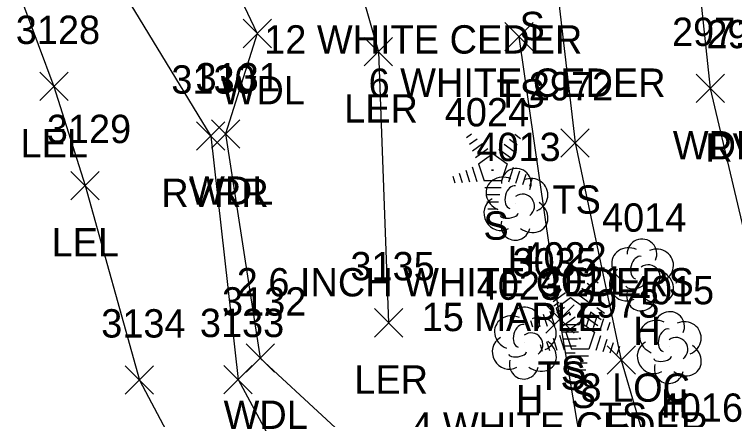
# Model space of a CAD drawing. Extents: x 1461855 to 1464118, y 556196 to 557441.
# Drawn here: x 1462111.2 to 1462162, y 556638.7 to 556667.3 of the extents above; entities that cross this region are included whole.
import ezdxf

# ---------------------------------------------------------------- set-up
doc = ezdxf.new("R2010")
doc.units = 0
for name, color, linetype in [('L_A', 7, 'Continuous'), ('L_C', 7, 'Continuous'), ('L_I', 7, 'Continuous'), ('L_TIC', 7, 'Continuous'), ('LARO', 7, 'Continuous'), ('LAWA', 7, 'Continuous'), ('LAWE', 7, 'Continuous'), ('LELB', 7, 'Continuous'), ('LTC', 7, 'Continuous'), ('LTD', 7, 'Continuous')]:
    doc.layers.add(name, color=color, linetype=linetype)

msp = doc.modelspace()

# ---------------------------------------------------------------- linework, layer by layer
at = {"layer": 'L_TIC'}
for points in [[(1462127.342, 556664.944), (1462129.342, 556666.944)], [(1462129.342, 556664.944), (1462127.342, 556666.944)], [(1462145.813, 556664.717), (1462147.813, 556666.717)], [(1462147.813, 556664.717), (1462145.813, 556666.717)], [(1462135.891, 556663.654), (1462137.891, 556665.654)], [(1462137.891, 556663.654), (1462135.891, 556665.654)], [(1462113.001, 556661.205), (1462115.001, 556663.205)], [(1462115.001, 556661.205), (1462113.001, 556663.205)], [(1462159.296, 556661.064), (1462161.296, 556663.064)], [(1462161.296, 556661.064), (1462159.296, 556663.064)], [(1462125.113, 556657.86), (1462127.113, 556659.86)], [(1462127.113, 556657.86), (1462125.113, 556659.86)], [(1462124.062, 556657.7), (1462126.062, 556659.7)], [(1462126.062, 556657.7), (1462124.062, 556659.7)], [(1462149.759, 556657.223), (1462151.759, 556659.223)], [(1462151.759, 556657.223), (1462149.759, 556659.223)], [(1462115.197, 556654.209), (1462117.197, 556656.209)], [(1462117.197, 556654.209), (1462115.197, 556656.209)], [(1462148.691, 556644.796), (1462150.691, 556646.796)], [(1462150.691, 556644.796), (1462148.691, 556646.796)], [(1462136.608, 556644.525), (1462138.608, 556646.525)], [(1462138.608, 556644.525), (1462136.608, 556646.525)], [(1462127.549, 556642.037), (1462129.549, 556644.037)], [(1462129.549, 556642.037), (1462127.549, 556644.037)], [(1462153.021, 556641.891), (1462155.021, 556643.891)], [(1462155.021, 556641.891), (1462153.021, 556643.891)], [(1462119.026, 556640.487), (1462121.026, 556642.487)], [(1462121.026, 556640.487), (1462119.026, 556642.487)], [(1462125.988, 556640.518), (1462127.988, 556642.518)], [(1462127.988, 556640.518), (1462125.988, 556642.518)]]:
    msp.add_lwpolyline(points, dxfattribs=at)
at = {"layer": 'LARO'}
for points in [[(1462142.293, 556708.494), (1462140.234, 556698.475), (1462135.169, 556692.385), (1462132.829, 556689.631), (1462132.282, 556680.721), (1462136.891, 556664.654), (1462137.608, 556645.525)], [(1462108.44, 556677.046), (1462114.001, 556662.205), (1462116.197, 556655.209), (1462120.026, 556641.487), (1462125.669, 556630.824), (1462129.521, 556622.314), (1462133.504, 556616.498), (1462125.817, 556618.515), (1462129.13, 556595.188), (1462130.737, 556586.238), (1462133.324, 556585.263), (1462130.889, 556567.664), (1462134.873, 556566.28), (1462133.035, 556549.7)]]:
    msp.add_lwpolyline(points, dxfattribs=at)
at = {"layer": 'LAWA'}
for points in [[(1462144.486, 556687.662), (1462132.829, 556689.631), (1462118.64, 556686.34), (1462128.342, 556665.944), (1462126.113, 556658.86), (1462128.549, 556643.037), (1462142.595, 556630.056)], [(1462144.486, 556687.662), (1462148.927, 556688.411), (1462158.302, 556680.826), (1462160.296, 556662.064), (1462165.164, 556641.464), (1462166.507, 556625.891), (1462158.371, 556628.049), (1462154.015, 556627.718), (1462147.126, 556625.455), (1462144.242, 556624.514), (1462143.044, 556630.161)]]:
    msp.add_lwpolyline(points, dxfattribs=at)
at = {"layer": 'LAWE'}
msp.add_lwpolyline([(1462120.691, 556737.434), (1462122.423, 556720.718), (1462119.992, 556701.198), (1462119.681, 556688.809), (1462118.64, 556686.34), (1462114.371, 556676.303), (1462125.062, 556658.7), (1462126.988, 556641.518), (1462131.288, 556633.529), (1462137.745, 556624.648), (1462141.077, 556615.301), (1462145.141, 556602.946), (1462161.881, 556553.375), (1462138.756, 556543.397)], dxfattribs=at)
at = {"layer": 'LELB'}
for points in [[(1462148.927, 556688.411), (1462148.332, 556679.235), (1462150.759, 556658.223), (1462154.021, 556642.891), (1462158.371, 556628.049), (1462165.363, 556612.34), (1462167.802, 556604.927)], [(1462152.193, 556630.886), (1462149.691, 556645.796), (1462146.813, 556665.717)]]:
    msp.add_lwpolyline(points, dxfattribs=at)
at = {"layer": 'LTC'}
for p, q in [((1462143.106, 556658.596), (1462143.461, 556658.854)), ((1462146.505, 556658.837), (1462146.924, 556658.532)), ((1462143.316, 556658.131), (1462143.845, 556658.515)), ((1462146.133, 556658.488), (1462146.683, 556658.089)), ((1462143.525, 556657.665), (1462144.229, 556658.176)), ((1462143.735, 556657.199), (1462144.613, 556657.837)), ((1462145.763, 556658.14), (1462146.442, 556657.646)), ((1462143.96, 556656.744), (1462144.971, 556657.479)), ((1462144.971, 556657.479), (1462145.968, 556656.754)), ((1462145.391, 556657.792), (1462146.201, 556657.203)), ((1462143.05, 556656.309), (1462143.321, 556655.473)), ((1462143.505, 556656.525), (1462143.836, 556655.506)), ((1462143.96, 556656.744), (1462144.347, 556655.551)), ((1462145.968, 556656.754), (1462145.577, 556655.551)), ((1462146.406, 556656.483), (1462146.068, 556655.443)), ((1462142.139, 556655.875), (1462142.291, 556655.407)), ((1462142.594, 556656.092), (1462142.806, 556655.44)), ((1462146.85, 556656.232), (1462146.563, 556655.348)), ((1462147.295, 556655.982), (1462147.058, 556655.253)), ((1462145.577, 556655.551), (1462144.347, 556655.551)), ((1462147.739, 556655.732), (1462147.553, 556655.158)), ((1462145.539, 556655.051), (1462144.394, 556655.051)), ((1462145.455, 556654.551), (1462144.467, 556654.551)), ((1462145.371, 556654.051), (1462144.54, 556654.051)), ((1462145.288, 556653.551), (1462144.613, 556653.551)), ((1462148.579, 556648.421), (1462148.933, 556648.679)), ((1462148.788, 556647.956), (1462149.318, 556648.34)), ((1462151.606, 556648.313), (1462152.155, 556647.914)), ((1462151.977, 556648.661), (1462152.396, 556648.357)), ((1462148.998, 556647.49), (1462149.702, 556648.001)), ((1462149.208, 556647.024), (1462150.086, 556647.662)), ((1462151.235, 556647.965), (1462151.914, 556647.471)), ((1462149.432, 556646.569), (1462150.444, 556647.304)), ((1462150.444, 556647.304), (1462151.441, 556646.579)), ((1462150.864, 556647.616), (1462151.673, 556647.028)), ((1462149.267, 556646.718), (1462149.622, 556646.976)), ((1462152.666, 556646.959), (1462153.085, 556646.654)), ((1462148.978, 556646.35), (1462149.308, 556645.331)), ((1462149.432, 556646.569), (1462149.819, 556645.376)), ((1462149.477, 556646.253), (1462150.006, 556646.637)), ((1462149.687, 556645.787), (1462150.39, 556646.298)), ((1462151.441, 556646.579), (1462151.05, 556645.376)), ((1462151.878, 556646.308), (1462151.54, 556645.268)), ((1462151.924, 556646.262), (1462152.603, 556645.768)), ((1462152.294, 556646.61), (1462152.844, 556646.211)), ((1462147.611, 556645.7), (1462147.763, 556645.232)), ((1462148.067, 556645.917), (1462148.278, 556645.265)), ((1462148.522, 556646.134), (1462148.793, 556645.298)), ((1462149.896, 556645.321), (1462150.774, 556645.959)), ((1462151.552, 556645.914), (1462152.362, 556645.325)), ((1462152.323, 556646.057), (1462152.035, 556645.173)), ((1462152.768, 556645.807), (1462152.53, 556645.078)), ((1462151.05, 556645.376), (1462149.819, 556645.376)), ((1462150.121, 556644.866), (1462151.132, 556645.601)), ((1462151.132, 556645.601), (1462152.129, 556644.876)), ((1462153.212, 556645.557), (1462153.025, 556644.983)), ((1462149.666, 556644.647), (1462149.997, 556643.628)), ((1462151.011, 556644.876), (1462149.867, 556644.876)), ((1462150.121, 556644.866), (1462150.508, 556643.673)), ((1462152.129, 556644.876), (1462151.738, 556643.673)), ((1462148.755, 556644.214), (1462148.967, 556643.562)), ((1462149.211, 556644.431), (1462149.482, 556643.595)), ((1462150.928, 556644.376), (1462149.939, 556644.376)), ((1462152.567, 556644.605), (1462152.229, 556643.565)), ((1462153.011, 556644.354), (1462152.724, 556643.47)), ((1462153.456, 556644.104), (1462153.219, 556643.375)), ((1462148.3, 556643.997), (1462148.452, 556643.529)), ((1462150.844, 556643.876), (1462150.012, 556643.876)), ((1462151.738, 556643.673), (1462150.508, 556643.673)), ((1462153.9, 556643.854), (1462153.714, 556643.28)), ((1462150.76, 556643.376), (1462150.085, 556643.376)), ((1462151.7, 556643.173), (1462150.555, 556643.173)), ((1462151.616, 556642.673), (1462150.628, 556642.673)), ((1462151.532, 556642.173), (1462150.701, 556642.173)), ((1462151.449, 556641.673), (1462150.774, 556641.673))]:
    msp.add_line(p, q, dxfattribs=at)
at = {"layer": 'LTD'}
for p, q in [((1462146.571, 556653.939), (1462146.571, 556653.939)), ((1462146.571, 556653.939), (1462146.571, 556653.939)), ((1462155.435, 556648.956), (1462155.435, 556648.956)), ((1462155.435, 556648.956), (1462155.435, 556648.956)), ((1462147.164, 556644.149), (1462147.164, 556644.149)), ((1462147.164, 556644.149), (1462147.164, 556644.149)), ((1462157.392, 556643.832), (1462157.392, 556643.832)), ((1462157.392, 556643.832), (1462157.392, 556643.832))]:
    msp.add_line(p, q, dxfattribs=at)
for centre in [(1462146.618, 556655.372), (1462155.482, 556650.39), (1462147.211, 556645.583), (1462157.439, 556645.266)]:
    msp.add_arc(centre, 1.047, 335.5272, 180.9563, dxfattribs=at)
for centre, major_axis, ratio, start_param, end_param in [((1462145.78, 556654.605), (1.21, -0.512), 0.895232, 1.570796, 4.712389), ((1462147.613, 556654.522), (-1.141, -0.483), 0.949671, 1.570796, 4.712389), ((1462146.363, 556654.397), (-0.208, -0.792), 0.645439, 3.141593, 6.283185), ((1462145.488, 556653.23), (0.584, -1.042), 0.959034, 3.141593, 6.283185), ((1462147.071, 556653.772), (-0.5, 0.667), 0.989748, 3.141593, 6.283185), ((1462147.571, 556653.105), (-1.09, 0.792), 0.841452, 1.570796, 4.712389), ((1462146.113, 556653.188), (-0.625, -0.083), 0.423636, 0, 3.141593), ((1462146.572, 556652.439), (0.265, 1.061), 0.942809, 1.570796, 4.712389), ((1462154.644, 556649.623), (1.21, -0.512), 0.895232, 1.570796, 4.712389), ((1462156.477, 556649.54), (-1.141, -0.483), 0.949671, 1.570796, 4.712389), ((1462155.227, 556649.415), (-0.208, -0.792), 0.645439, 3.141593, 6.283185), ((1462155.935, 556648.79), (-0.5, 0.667), 0.989748, 3.141593, 6.283185), ((1462154.352, 556648.248), (0.584, -1.042), 0.959034, 3.141593, 6.283185), ((1462156.435, 556648.123), (-1.09, 0.792), 0.841452, 1.570796, 4.712389), ((1462154.977, 556648.206), (-0.625, -0.083), 0.423636, 0, 3.141593), ((1462155.436, 556647.456), (0.265, 1.061), 0.942809, 1.570796, 4.712389), ((1462146.373, 556644.815), (1.21, -0.512), 0.895232, 1.570796, 4.712389), ((1462148.206, 556644.732), (-1.141, -0.483), 0.949671, 1.570796, 4.712389), ((1462156.6, 556644.499), (1.21, -0.512), 0.895232, 1.570796, 4.712389), ((1462158.433, 556644.416), (-1.141, -0.483), 0.949671, 1.570796, 4.712389), ((1462146.956, 556644.607), (-0.208, -0.792), 0.645439, 3.141593, 6.283185), ((1462157.183, 556644.29), (-0.208, -0.792), 0.645439, 3.141593, 6.283185), ((1462147.665, 556643.982), (-0.5, 0.667), 0.989748, 3.141593, 6.283185), ((1462146.081, 556643.44), (0.584, -1.042), 0.959034, 3.141593, 6.283185), ((1462148.165, 556643.316), (-1.09, 0.792), 0.841452, 1.570796, 4.712389), ((1462156.309, 556643.124), (0.584, -1.042), 0.959034, 3.141593, 6.283185), ((1462157.892, 556643.666), (-0.5, 0.667), 0.989748, 3.141593, 6.283185), ((1462158.392, 556642.999), (-1.09, 0.792), 0.841452, 1.570796, 4.712389), ((1462146.706, 556643.399), (-0.625, -0.083), 0.423636, 0, 3.141593), ((1462156.934, 556643.082), (-0.625, -0.083), 0.423636, 0, 3.141593), ((1462147.165, 556642.649), (0.265, 1.061), 0.942809, 1.570796, 4.712389), ((1462157.392, 556642.332), (0.265, 1.061), 0.942809, 1.570796, 4.712389)]:
    msp.add_ellipse(centre, major_axis=major_axis, ratio=ratio, start_param=start_param, end_param=end_param, dxfattribs=at)

# ---------------------------------------------------------------- texts
at = {"layer": 'L_A'}
for s, p in [('S', (1462146.849, 556665.474)), ('WDL', (1462125.759, 556660.944)), ('TS', (1462145.222, 556660.717)), ('LER', (1462134.473, 556659.654)), ('LEL', (1462111.638, 556657.205)), ('WDR', (1462157.659, 556657.064)), ('RVRL', (1462159.943, 556656.905)), ('WDL', (1462123.53, 556653.86)), ('RVRR', (1462121.574, 556653.7)), ('TS', (1462149.168, 556653.223)), ('S', (1462144.297, 556651.388)), ('LEL', (1462113.835, 556650.209)), ('H', (1462146.004, 556648.939)), ('H', (1462154.868, 556643.956)), ('S', (1462149.769, 556641.213)), ('TS', (1462148.1, 556640.796)), ('LER', (1462135.19, 556640.525)), ('H', (1462146.598, 556639.149)), ('S', (1462150.458, 556639.51)), ('H', (1462156.825, 556638.832)), ('WDL', (1462125.966, 556638.037)), ('TS', (1462152.43, 556637.891))]:
    msp.add_text(s, height=2, dxfattribs=at).set_placement(p)
at = {"layer": 'L_C'}
for s, p in [('12 WHITE CEDER', (1462128.834, 556664.527)), ('6 WHITE CEDER', (1462136.195, 556661.474)), ('2 6 INCH WHITE CEDERS', (1462126.895, 556647.388)), ('15 MAPLE', (1462139.941, 556644.939)), ('8 LOC', (1462151.144, 556639.956)), ('4 WHITE CEDER', (1462139.21, 556637.213))]:
    msp.add_text(s, height=2, dxfattribs=at).set_placement(p)
at = {"layer": 'L_I'}
for s, p in [('3128', (1462111.308, 556665.205)), ('2971', (1462157.603, 556665.064)), ('2970', (1462160.029, 556664.905)), ('3130', (1462122.282, 556661.7)), ('3131', (1462123.987, 556661.86)), ('2972', (1462147.499, 556661.223)), ('4024', (1462141.573, 556659.388)), ('3129', (1462113.496, 556658.209)), ('4013', (1462143.8, 556656.939)), ('4014', (1462152.664, 556651.956)), ('4022', (1462147.045, 556649.213)), ('3035', (1462146.352, 556648.796)), ('3135', (1462134.915, 556648.525)), ('4021', (1462148.301, 556647.51)), ('4023', (1462143.826, 556647.149)), ('4015', (1462154.62, 556646.832)), ('3132', (1462125.856, 556646.037)), ('2973', (1462150.761, 556645.891)), ('3134', (1462117.333, 556644.487)), ('3133', (1462124.295, 556644.518)), ('4016', (1462156.66, 556638.54))]:
    msp.add_text(s, height=2, dxfattribs=at).set_placement(p)
at = {"layer": 'LTC'}
for p in [(1462144.854, 556656.492), (1462150.326, 556646.317), (1462151.015, 556644.614)]:
    msp.add_text('.', height=1.037, rotation=270, dxfattribs=at).set_placement(p)

doc.saveas('drawing.dxf')
